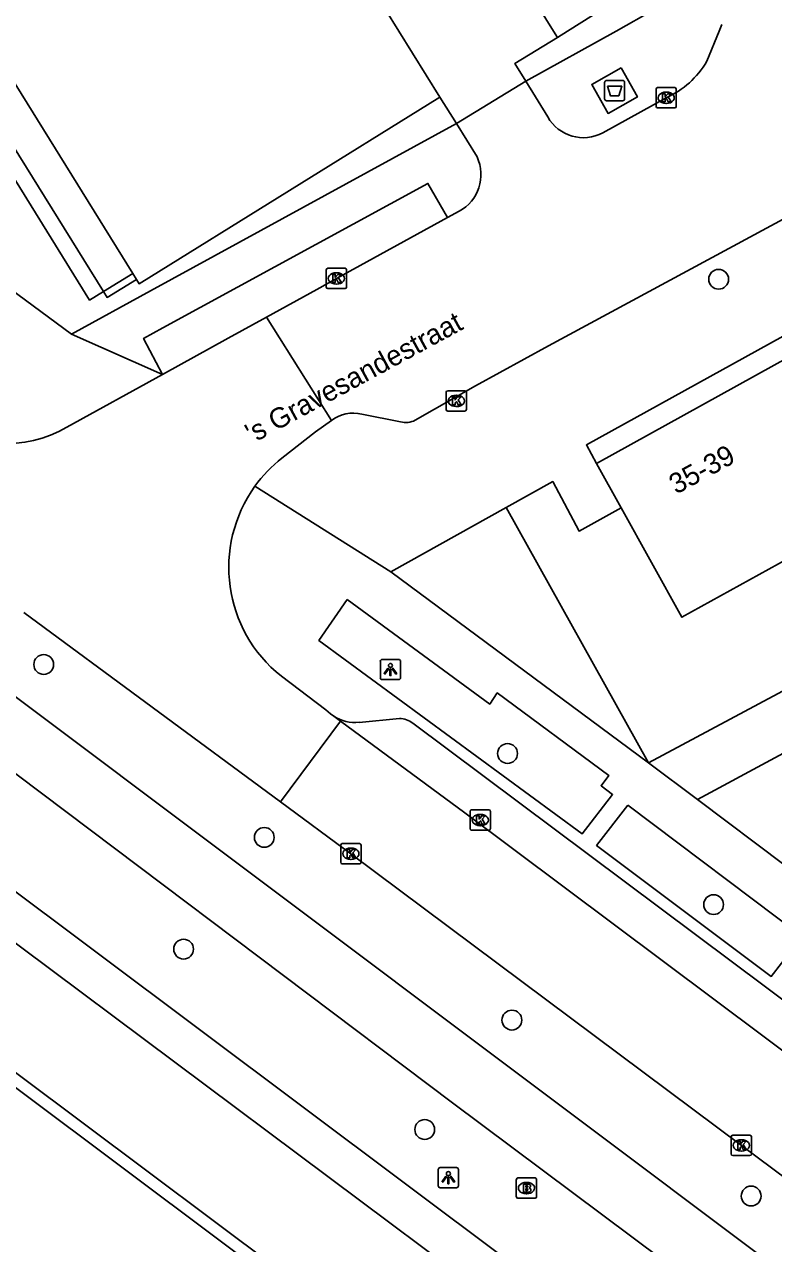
# Model space of a CAD drawing. Extents: x 159888 to 160757, y 384031 to 384746.
# Drawn here: x 160110.7 to 160147.6, y 384440.1 to 384500.3 of the extents above; entities that cross this region are included whole.
import ezdxf

# ---------------------------------------------------------------- set-up
doc = ezdxf.new("R2010")
doc.units = 0
for name, color, linetype in [('IMGEO_Afval_apart_plaats', 7, 'Continuous'), ('IMGEO_Boom', 7, 'Continuous'), ('IMGEO_Brandkraan', 7, 'Continuous'), ('IMGEO_Fietspad_gesloten', 7, 'Continuous'), ('IMGEO_Groenvoorziening', 7, 'Continuous'), ('IMGEO_Haag', 7, 'Continuous'), ('IMGEO_Hek', 7, 'Continuous'), ('IMGEO_Kolk', 7, 'Continuous'), ('IMGEO_Lichtpunt', 7, 'Continuous'), ('IMGEO_Openbare_ruimte_label', 7, 'Continuous'), ('IMGEO_Pand', 7, 'Continuous'), ('IMGEO_Pand_nummerreeks', 7, 'Continuous'), ('IMGEO_Parkeervlak_open', 7, 'Continuous'), ('IMGEO_Rijbaan_lokaal_open', 7, 'Continuous'), ('IMGEO_Voetpad_gesloten', 7, 'Continuous'), ('IMGEO_Voetpad_halfverhard', 7, 'Continuous'), ('IMGEO_Voetpad_open', 7, 'Continuous')]:
    doc.layers.add(name, color=color, linetype=linetype)

msp = doc.modelspace()

# ---------------------------------------------------------------- linework, layer by layer
at = {"layer": 'IMGEO_Afval_apart_plaats'}
for p, q in [((160139.395, 384497.556), (160140.185, 384497.556)), ((160140.185, 384497.556), (160139.395, 384497.556)), ((160139.295, 384496.656), (160139.295, 384497.456)), ((160139.295, 384497.456), (160139.295, 384496.656)), ((160140.285, 384497.456), (160140.285, 384496.656)), ((160140.285, 384496.656), (160140.285, 384497.456)), ((160140.185, 384496.556), (160139.395, 384496.556)), ((160139.395, 384496.556), (160140.185, 384496.556))]:
    msp.add_line(p, q, dxfattribs=at)
msp.add_lwpolyline([(160139.438, 384497.27), (160140.142, 384497.27), (160139.993, 384496.8), (160139.587, 384496.8), (160139.438, 384497.27)], dxfattribs=at)
for centre, start, end in [((160139.395, 384497.456), 90, 180), ((160139.395, 384497.456), 90, 180), ((160140.185, 384497.456), 0, 90), ((160140.185, 384497.456), 360, 90), ((160139.395, 384496.656), 180, 270), ((160139.395, 384496.656), 180, 270), ((160140.185, 384496.656), 270, 0), ((160140.185, 384496.656), 270, 0)]:
    msp.add_arc(centre, 0.1, start, end, dxfattribs=at)
at = {"layer": 'IMGEO_Boom'}
for centre in [(160144.928, 384487.736), (160111.605, 384468.701), (160134.505, 384464.304), (160122.495, 384460.16), (160144.679, 384456.839), (160118.512, 384454.638), (160134.719, 384451.131), (160130.417, 384445.725), (160146.532, 384442.44)]:
    msp.add_circle(centre, 0.489, dxfattribs=at)
at = {"layer": 'IMGEO_Brandkraan'}
for p, q in [((160134.939, 384442.406), (160134.939, 384443.258)), ((160135.014, 384443.332), (160135.866, 384443.332)), ((160135.94, 384443.258), (160135.94, 384442.406)), ((160135.427, 384443.112), (160135.452, 384443.112)), ((160135.866, 384442.332), (160135.014, 384442.332)), ((160135.45, 384442.552), (160135.425, 384442.552))]:
    msp.add_line(p, q, dxfattribs=at)
for points in [[(160134.939, 384442.406), (160134.939, 384443.258)], [(160135.014, 384443.332), (160135.866, 384443.332)], [(160135.94, 384443.258), (160135.94, 384442.406)], [(160135.287, 384443.032), (160135.287, 384442.632), (160135.5, 384442.632)], [(160135.518, 384443.032), (160135.287, 384443.032)], [(160135.466, 384442.951), (160135.412, 384442.951), (160135.412, 384442.875)], [(160135.412, 384442.875), (160135.465, 384442.875)], [(160135.474, 384442.799), (160135.412, 384442.799), (160135.412, 384442.718)], [(160135.412, 384442.718), (160135.474, 384442.718)], [(160135.866, 384442.332), (160135.014, 384442.332)]]:
    msp.add_lwpolyline(points, dxfattribs=at)
for centre, radius, start, end in [((160135.016, 384443.256), 0.0765, 91.55205, 178.44795), ((160135.016, 384443.256), 0.0765, 91.55205, 178.44795), ((160135.864, 384443.256), 0.0765, 1.55205, 88.44795), ((160135.864, 384443.256), 0.0765, 1.55205, 88.44795), ((160135.467, 384442.913), 0.0379, 267.82845, 90.93552), ((160135.475, 384442.758), 0.0404, 269.87594, 90.50774), ((160135.506, 384442.883), 0.251, 268.66757, 293.53466), ((160135.522, 384442.887), 0.145, 59.4692, 91.53667), ((160135.547, 384442.934), 0.0922, 285.51372, 58.15012), ((160135.552, 384442.742), 0.105, 301.31148, 78.98903), ((160135.016, 384442.408), 0.0765, 181.55205, 268.44795), ((160135.016, 384442.408), 0.0765, 181.55205, 268.44795), ((160135.864, 384442.408), 0.0765, 271.55205, 358.44795), ((160135.864, 384442.408), 0.0765, 271.55205, 358.44795)]:
    msp.add_arc(centre, radius, start, end, dxfattribs=at)
for centre, major_axis, ratio, start_param, end_param in [((160135.426, 384442.832), (-0.387, 0.002), 0.722429, 4.712389, 7.853982), ((160135.451, 384442.832), (-0.39, 0.002), 0.717154, 1.570796, 4.712389)]:
    msp.add_ellipse(centre, major_axis=major_axis, ratio=ratio, start_param=start_param, end_param=end_param, dxfattribs=at)
at = {"layer": 'IMGEO_Fietspad_gesloten'}
for points in [[(160176.501, 384417.329), (160108.604, 384468.298), (160108.46, 384468.406)], [(160106.735, 384465.918), (160131.786, 384447.047), (160174.693, 384414.967)]]:
    msp.add_lwpolyline(points, dxfattribs=at)
at = {"layer": 'IMGEO_Groenvoorziening'}
msp.add_lwpolyline([(160134.442, 384476.461), (160141.469, 384463.844)], dxfattribs=at)
at = {"layer": 'IMGEO_Haag'}
for points in [[(160100.768, 384455.61), (160135.944, 384429.265)], [(160100.548, 384455.024), (160135.218, 384429.059), (160121.596, 384394.526)]]:
    msp.add_lwpolyline(points, dxfattribs=at)
at = {"layer": 'IMGEO_Hek'}
msp.add_lwpolyline([(160121.596, 384394.526), (160135.218, 384429.059), (160100.548, 384455.024)], dxfattribs=at)
at = {"layer": 'IMGEO_Kolk'}
for p, q in [((160141.837, 384496.276), (160141.837, 384497.128)), ((160141.912, 384497.202), (160142.764, 384497.202)), ((160142.325, 384496.982), (160142.35, 384496.982)), ((160142.838, 384497.128), (160142.838, 384496.276)), ((160142.348, 384496.422), (160142.323, 384496.422)), ((160142.764, 384496.202), (160141.912, 384496.202)), ((160125.555, 384487.35), (160125.555, 384488.202)), ((160125.63, 384488.276), (160126.482, 384488.276)), ((160126.043, 384488.056), (160126.068, 384488.056)), ((160126.556, 384488.202), (160126.556, 384487.35)), ((160126.482, 384487.276), (160125.63, 384487.276)), ((160126.066, 384487.496), (160126.041, 384487.496)), ((160131.474, 384481.3), (160131.474, 384482.152)), ((160131.549, 384482.226), (160132.401, 384482.226)), ((160131.962, 384482.006), (160131.987, 384482.006)), ((160132.475, 384482.152), (160132.475, 384481.3)), ((160132.401, 384481.226), (160131.549, 384481.226)), ((160131.985, 384481.446), (160131.96, 384481.446)), ((160132.656, 384460.592), (160132.656, 384461.444)), ((160132.731, 384461.518), (160133.583, 384461.518)), ((160133.657, 384461.444), (160133.657, 384460.592)), ((160133.167, 384460.738), (160133.142, 384460.738)), ((160133.144, 384461.298), (160133.169, 384461.298)), ((160133.583, 384460.518), (160132.731, 384460.518)), ((160126.269, 384458.927), (160126.269, 384459.779)), ((160126.344, 384459.853), (160127.196, 384459.853)), ((160126.757, 384459.633), (160126.782, 384459.633)), ((160127.27, 384459.779), (160127.27, 384458.927)), ((160126.78, 384459.073), (160126.755, 384459.073)), ((160127.196, 384458.853), (160126.344, 384458.853)), ((160145.547, 384444.516), (160145.547, 384445.368)), ((160145.622, 384445.442), (160146.474, 384445.442)), ((160146.035, 384445.222), (160146.06, 384445.222)), ((160146.548, 384445.368), (160146.548, 384444.516)), ((160146.058, 384444.662), (160146.033, 384444.662)), ((160146.474, 384444.442), (160145.622, 384444.442))]:
    msp.add_line(p, q, dxfattribs=at)
for points in [[(160141.837, 384496.276), (160141.837, 384497.128)], [(160141.912, 384497.202), (160142.764, 384497.202)], [(160142.158, 384496.902), (160142.281, 384496.902), (160142.281, 384496.751), (160142.411, 384496.902), (160142.575, 384496.902), (160142.429, 384496.751), (160142.582, 384496.502), (160142.43, 384496.502), (160142.345, 384496.666), (160142.281, 384496.599), (160142.281, 384496.502), (160142.158, 384496.502), (160142.158, 384496.902)], [(160142.838, 384497.128), (160142.838, 384496.276)], [(160142.764, 384496.202), (160141.912, 384496.202)], [(160125.555, 384487.35), (160125.555, 384488.202)], [(160125.63, 384488.276), (160126.482, 384488.276)], [(160125.876, 384487.976), (160125.999, 384487.976), (160125.999, 384487.825), (160126.129, 384487.976), (160126.293, 384487.976), (160126.147, 384487.825), (160126.3, 384487.576), (160126.148, 384487.576), (160126.063, 384487.74), (160125.999, 384487.673), (160125.999, 384487.576), (160125.876, 384487.576), (160125.876, 384487.976)], [(160126.556, 384488.202), (160126.556, 384487.35)], [(160126.482, 384487.276), (160125.63, 384487.276)], [(160131.474, 384481.3), (160131.474, 384482.152)], [(160131.549, 384482.226), (160132.401, 384482.226)], [(160131.795, 384481.926), (160131.918, 384481.926), (160131.918, 384481.775), (160132.048, 384481.926), (160132.212, 384481.926), (160132.066, 384481.775), (160132.219, 384481.526), (160132.067, 384481.526), (160131.982, 384481.69), (160131.918, 384481.623), (160131.918, 384481.526), (160131.795, 384481.526), (160131.795, 384481.926)], [(160132.475, 384482.152), (160132.475, 384481.3)], [(160132.401, 384481.226), (160131.549, 384481.226)], [(160132.656, 384460.592), (160132.656, 384461.444)], [(160132.731, 384461.518), (160133.583, 384461.518)], [(160133.657, 384461.444), (160133.657, 384460.592)], [(160132.977, 384461.218), (160133.1, 384461.218), (160133.1, 384461.067), (160133.23, 384461.218), (160133.394, 384461.218), (160133.248, 384461.067), (160133.401, 384460.818), (160133.249, 384460.818), (160133.164, 384460.982), (160133.1, 384460.915), (160133.1, 384460.818), (160132.977, 384460.818), (160132.977, 384461.218)], [(160133.583, 384460.518), (160132.731, 384460.518)], [(160126.269, 384458.927), (160126.269, 384459.779)], [(160126.344, 384459.853), (160127.196, 384459.853)], [(160126.59, 384459.553), (160126.713, 384459.553), (160126.713, 384459.402), (160126.843, 384459.553), (160127.007, 384459.553), (160126.861, 384459.402), (160127.014, 384459.153), (160126.862, 384459.153), (160126.777, 384459.317), (160126.713, 384459.25), (160126.713, 384459.153), (160126.59, 384459.153), (160126.59, 384459.553)], [(160127.27, 384459.779), (160127.27, 384458.927)], [(160127.196, 384458.853), (160126.344, 384458.853)], [(160145.547, 384444.516), (160145.547, 384445.368)], [(160145.622, 384445.442), (160146.474, 384445.442)], [(160145.868, 384445.142), (160145.991, 384445.142), (160145.991, 384444.991), (160146.121, 384445.142), (160146.285, 384445.142), (160146.139, 384444.991), (160146.292, 384444.742), (160146.14, 384444.742), (160146.055, 384444.906), (160145.991, 384444.839), (160145.991, 384444.742), (160145.868, 384444.742), (160145.868, 384445.142)], [(160146.548, 384445.368), (160146.548, 384444.516)], [(160146.474, 384444.442), (160145.622, 384444.442)]]:
    msp.add_lwpolyline(points, dxfattribs=at)
for centre, start, end in [((160141.914, 384497.126), 91.55205, 178.44795), ((160141.914, 384497.126), 91.55205, 178.44795), ((160142.762, 384497.126), 1.55205, 88.44795), ((160142.762, 384497.126), 1.55205, 88.44795), ((160141.914, 384496.278), 181.55205, 268.44795), ((160141.914, 384496.278), 181.55205, 268.44795), ((160142.762, 384496.278), 271.55205, 358.44795), ((160142.762, 384496.278), 271.55205, 358.44795), ((160125.632, 384488.2), 91.55205, 178.44795), ((160125.632, 384488.2), 91.55205, 178.44795), ((160126.48, 384488.2), 1.55205, 88.44795), ((160126.48, 384488.2), 1.55205, 88.44795), ((160125.632, 384487.352), 181.55205, 268.44795), ((160125.632, 384487.352), 181.55205, 268.44795), ((160126.48, 384487.352), 271.55205, 358.44795), ((160126.48, 384487.352), 271.55205, 358.44795), ((160131.551, 384482.15), 91.55205, 178.44795), ((160131.551, 384482.15), 91.55205, 178.44795), ((160132.399, 384482.15), 1.55205, 88.44795), ((160132.399, 384482.15), 1.55205, 88.44795), ((160131.551, 384481.302), 181.55205, 268.44795), ((160131.551, 384481.302), 181.55205, 268.44795), ((160132.399, 384481.302), 271.55205, 358.44795), ((160132.399, 384481.302), 271.55205, 358.44795), ((160132.733, 384461.442), 91.55205, 178.44795), ((160132.733, 384461.442), 91.55205, 178.44795), ((160133.581, 384461.442), 1.55205, 88.44795), ((160133.581, 384461.442), 1.55205, 88.44795), ((160132.733, 384460.594), 181.55205, 268.44795), ((160132.733, 384460.594), 181.55205, 268.44795), ((160133.581, 384460.594), 271.55205, 358.44795), ((160133.581, 384460.594), 271.55205, 358.44795), ((160126.346, 384459.777), 91.55205, 178.44795), ((160126.346, 384459.777), 91.55205, 178.44795), ((160127.194, 384459.777), 1.55205, 88.44795), ((160127.194, 384459.777), 1.55205, 88.44795), ((160126.346, 384458.929), 181.55205, 268.44795), ((160126.346, 384458.929), 181.55205, 268.44795), ((160127.194, 384458.929), 271.55205, 358.44795), ((160127.194, 384458.929), 271.55205, 358.44795), ((160145.624, 384445.366), 91.55205, 178.44795), ((160145.624, 384445.366), 91.55205, 178.44795), ((160146.472, 384445.366), 1.55205, 88.44795), ((160146.472, 384445.366), 1.55205, 88.44795), ((160145.624, 384444.518), 181.55205, 268.44795), ((160145.624, 384444.518), 181.55205, 268.44795), ((160146.472, 384444.518), 271.55205, 358.44795), ((160146.472, 384444.518), 271.55205, 358.44795)]:
    msp.add_arc(centre, 0.0765, start, end, dxfattribs=at)
for centre, major_axis, ratio, start_param, end_param in [((160142.324, 384496.702), (-0.387, 0.002), 0.722429, 4.712389, 7.853982), ((160142.349, 384496.702), (-0.39, 0.002), 0.717154, 1.570796, 4.712389), ((160126.042, 384487.776), (-0.387, 0.002), 0.722429, 4.712389, 7.853982), ((160126.067, 384487.776), (-0.39, 0.002), 0.717154, 1.570796, 4.712389), ((160131.961, 384481.726), (-0.387, 0.002), 0.722429, 4.712389, 7.853982), ((160131.986, 384481.726), (-0.39, 0.002), 0.717154, 1.570796, 4.712389), ((160133.143, 384461.018), (-0.387, 0.002), 0.722429, 4.712389, 7.853982), ((160133.168, 384461.018), (-0.39, 0.002), 0.717154, 1.570796, 4.712389), ((160126.756, 384459.353), (-0.387, 0.002), 0.722429, 4.712389, 7.853982), ((160126.781, 384459.353), (-0.39, 0.002), 0.717154, 1.570796, 4.712389), ((160146.034, 384444.942), (-0.387, 0.002), 0.722429, 4.712389, 7.853982), ((160146.059, 384444.942), (-0.39, 0.002), 0.717154, 1.570796, 4.712389)]:
    msp.add_ellipse(centre, major_axis=major_axis, ratio=ratio, start_param=start_param, end_param=end_param, dxfattribs=at)
at = {"layer": 'IMGEO_Lichtpunt'}
for p, q in [((160128.225, 384468.856), (160128.225, 384468.049)), ((160128.225, 384468.856), (160128.225, 384468.049)), ((160129.127, 384468.951), (160128.319, 384468.951)), ((160129.127, 384468.951), (160128.319, 384468.951)), ((160129.221, 384468.049), (160129.221, 384468.856)), ((160129.221, 384468.049), (160129.221, 384468.856)), ((160128.319, 384467.955), (160129.127, 384467.955)), ((160128.319, 384467.955), (160129.127, 384467.955)), ((160131.085, 384443.75), (160131.085, 384442.943)), ((160131.085, 384443.75), (160131.085, 384442.943)), ((160131.987, 384443.845), (160131.179, 384443.845)), ((160131.987, 384443.845), (160131.179, 384443.845)), ((160132.081, 384442.943), (160132.081, 384443.75)), ((160132.081, 384442.943), (160132.081, 384443.75)), ((160131.179, 384442.849), (160131.987, 384442.849)), ((160131.179, 384442.849), (160131.987, 384442.849))]:
    msp.add_line(p, q, dxfattribs=at)
for points in [[(160128.599, 384468.52), (160128.638, 384468.492), (160128.45, 384468.23), (160128.412, 384468.257), (160128.599, 384468.52)], [(160128.701, 384468.472), (160128.748, 384468.472), (160128.748, 384468.15), (160128.701, 384468.15), (160128.701, 384468.472)], [(160128.811, 384468.492), (160128.849, 384468.519), (160129.036, 384468.257), (160128.997, 384468.229), (160128.811, 384468.492)], [(160131.459, 384443.414), (160131.498, 384443.386), (160131.31, 384443.124), (160131.272, 384443.151), (160131.459, 384443.414)], [(160131.561, 384443.366), (160131.608, 384443.366), (160131.608, 384443.044), (160131.561, 384443.044), (160131.561, 384443.366)], [(160131.671, 384443.386), (160131.709, 384443.413), (160131.896, 384443.151), (160131.857, 384443.123), (160131.671, 384443.386)]]:
    msp.add_lwpolyline(points, dxfattribs=at)
for centre in [(160128.724, 384468.654), (160131.584, 384443.548)]:
    msp.add_circle(centre, 0.0994, dxfattribs=at)
for centre, start, end in [((160128.319, 384468.856), 90, 180), ((160128.319, 384468.856), 90, 180), ((160129.127, 384468.856), 0, 90), ((160129.127, 384468.856), 0, 90), ((160128.319, 384468.049), 180, 270), ((160128.319, 384468.049), 180, 270), ((160129.127, 384468.049), 270, 0), ((160129.127, 384468.049), 270, 360), ((160131.179, 384443.75), 90, 180), ((160131.179, 384443.75), 90, 180), ((160131.987, 384443.75), 0, 90), ((160131.987, 384443.75), 0, 90), ((160131.179, 384442.943), 180, 270), ((160131.179, 384442.943), 180, 270), ((160131.987, 384442.943), 270, 0), ((160131.987, 384442.943), 270, 360)]:
    msp.add_arc(centre, 0.0946, start, end, dxfattribs=at)
at = {"layer": 'IMGEO_Pand'}
for points in [[(160115.999, 384488.023), (160108.564, 384500), (160097.183, 384518.332), (160095.752, 384517.41)], [(160128.468, 384501.086), (160129.141, 384500), (160131.163, 384496.735)], [(160131.163, 384496.735), (160116.313, 384487.517), (160116.183, 384487.726)], [(160116.183, 384487.726), (160115.999, 384488.023)], [(160138.905, 384478.64), (160148.443, 384483.917)], [(160140.123, 384476.439), (160138.905, 384478.64)], [(160152.653, 384476.308), (160143.115, 384471.032), (160140.123, 384476.439)]]:
    msp.add_lwpolyline(points, dxfattribs=at)
at = {"layer": 'IMGEO_Parkeervlak_open'}
msp.add_lwpolyline([(160113.651, 384544.027), (160114.383, 384544.49), (160140.747, 384502.072), (160137.467, 384500), (160136.964, 384499.682)], dxfattribs=at)
at = {"layer": 'IMGEO_Rijbaan_lokaal_open'}
for points in [[(160136.964, 384499.682), (160136.767, 384500), (160133.491, 384505.278), (160125.564, 384518.085), (160117.707, 384530.736), (160110.676, 384542.144)], [(160173.174, 384504.351), (160165.309, 384500), (160136.525, 384484.446), (160132.921, 384482.467), (160129.945, 384480.77)], [(160145.086, 384500.328), (160144.953, 384500), (160144.344, 384498.503)], [(160136.964, 384499.682), (160134.865, 384498.396), (160135.403, 384497.521)], [(160131.986, 384495.431), (160135.403, 384497.521)], [(160136.49, 384495.754), (160135.403, 384497.521)], [(160131.986, 384495.431), (160131.163, 384496.735)], [(160142.338, 384496.702), (160139.206, 384494.967)], [(160133, 384493.777), (160131.986, 384495.431)], [(160131.541, 384490.783), (160132.111, 384491.096)], [(160122.601, 384485.866), (160125.089, 384487.237), (160126.056, 384487.775), (160131.541, 384490.783)], [(160117.465, 384483.034), (160120.71, 384484.823), (160122.601, 384485.866)], [(160125.809, 384480.749), (160122.601, 384485.866)], [(160117.465, 384483.034), (160112.74, 384480.43)], [(160123.361, 384478.894), (160125.026, 384480.19), (160125.809, 384480.749)], [(160129.224, 384480.695), (160127.316, 384481.07)], [(160123.3, 384461.916), (160110.627, 384471.276)], [(160123.337, 384468.124), (160125.534, 384466.455), (160125.764, 384466.268), (160125.926, 384466.149)], [(160126.25, 384465.909), (160125.926, 384466.149)], [(160126.25, 384465.909), (160123.3, 384461.916)], [(160197.083, 384412.292), (160191.755, 384416.654), (160181.504, 384424.593), (160132.389, 384461.371), (160126.25, 384465.909)], [(160194.701, 384407.79), (160192.098, 384409.987), (160187.785, 384413.501), (160183.142, 384417.08), (160178.248, 384420.845), (160172.683, 384425.02), (160155.276, 384438.063), (160146.048, 384444.942), (160126.77, 384459.353), (160123.3, 384461.916)]]:
    msp.add_lwpolyline(points, dxfattribs=at)
for centre, radius, start, end in [((160140.501, 384500.766), 4.46, 294.3261, 329.5093), ((160138.255, 384496.764), 2.033, 209.7843, 297.89629), ((160131.138, 384492.907), 2.056, 298.26007, 25.04965), ((160109.728, 384485.549), 5.94, 232.76784, 300.47483), ((160126.889, 384479.377), 1.746, 75.83702, 128.21224), ((160129.486, 384481.675), 1.015, 255.0106, 296.86675), ((160127.613, 384473.5), 6.868, 128.24756, 144.28911), ((160127.613, 384473.499), 6.869, 144.28521, 231.4995)]:
    msp.add_arc(centre, radius, start, end, dxfattribs=at)
at = {"layer": 'IMGEO_Voetpad_gesloten'}
for points in [[(160140.108, 384498.184), (160140.92, 384496.747), (160139.472, 384495.929), (160138.66, 384497.366), (160140.108, 384498.184)], [(160197.935, 384421.095), (160223.27, 384462.707), (160222.659, 384463.811), (160194.145, 384491.56), (160192.947, 384491.75), (160157.338, 384472.343), (160141.469, 384463.844)], [(160143.881, 384462.027), (160166.157, 384474.038)], [(160141.469, 384463.844), (160143.881, 384462.027)]]:
    msp.add_lwpolyline(points, dxfattribs=at)
at = {"layer": 'IMGEO_Voetpad_halfverhard'}
for points in [[(160166.207, 384415.5), (160147.116, 384429.811), (160144.684, 384431.634), (160104.064, 384462.082)], [(160102.826, 384460.451), (160140.939, 384431.966)]]:
    msp.add_lwpolyline(points, dxfattribs=at)
at = {"layer": 'IMGEO_Voetpad_open'}
for points in [[(160112.975, 384485.03), (160092.698, 384500.015), (160074.056, 384513.832), (160058.403, 384525.598), (160044.048, 384536.578), (160039.158, 384540.572)], [(160095.752, 384517.41), (160106.562, 384500), (160114.554, 384487.129)], [(160196.41, 384511.643), (160175.365, 384500), (160138.4, 384479.55), (160138.905, 384478.64)], [(160135.403, 384497.521), (160139.861, 384500), (160141.73, 384501.039)], [(160131.986, 384495.431), (160116.883, 384487.168), (160112.975, 384485.03)], [(160114.554, 384487.129), (160113.873, 384486.708), (160109.069, 384494.434)], [(160117.465, 384483.034), (160116.532, 384484.812), (160117.493, 384485.333), (160130.574, 384492.472), (160131.541, 384490.783)], [(160115.999, 384488.023), (160114.554, 384487.129)], [(160114.554, 384487.129), (160114.737, 384486.834), (160116.183, 384487.726)], [(160112.975, 384485.03), (160117.465, 384483.034)], [(160140.123, 384476.439), (160138.035, 384475.294), (160136.739, 384477.742), (160134.442, 384476.461)], [(160128.738, 384473.281), (160122.036, 384477.509)], [(160134.442, 384476.461), (160128.738, 384473.281)], [(160141.469, 384463.844), (160128.738, 384473.281)], [(160126.586, 384471.91), (160133.623, 384466.747), (160133.999, 384467.298), (160139.504, 384463.22), (160139.124, 384462.71), (160139.695, 384462.272), (160138.194, 384460.342), (160125.194, 384469.894), (160126.586, 384471.91)], [(160127.18, 384465.843), (160129.173, 384466.032)], [(160129.823, 384465.807), (160175.222, 384431.836), (160182.773, 384426.163), (160192.948, 384418.258), (160195.645, 384416.095)], [(160161.19, 384448.984), (160143.881, 384462.027)], [(160140.436, 384461.743), (160149.054, 384455.256), (160147.525, 384453.29), (160138.899, 384459.766), (160140.436, 384461.743)]]:
    msp.add_lwpolyline(points, dxfattribs=at)
for centre, radius, start, end in [((160126.978, 384467.737), 1.904, 236.47657, 276.09689), ((160129.132, 384464.862), 1.171, 53.82974, 87.98328)]:
    msp.add_arc(centre, radius, start, end, dxfattribs=at)

# ---------------------------------------------------------------- texts
at = {"layer": 'IMGEO_Openbare_ruimte_label'}
msp.add_text("'s Gravesandestraat", height=1, rotation=28.56472, dxfattribs=at).set_placement((160121.908, 384479.598))
at = {"layer": 'IMGEO_Pand_nummerreeks'}
msp.add_text('35-39', height=1, rotation=28.7398, dxfattribs=at).set_placement((160142.831, 384477.086))

doc.saveas('drawing.dxf')
